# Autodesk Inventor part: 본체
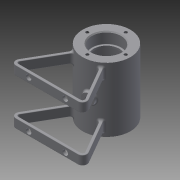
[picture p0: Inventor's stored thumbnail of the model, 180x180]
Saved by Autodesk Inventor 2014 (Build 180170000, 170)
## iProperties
Created: 2016-03
Part Number: 본체
Material: Generic
Document SubType Name: Modeling
Designer: user
Density: 1 g/cm^3
Appearance: Default
Author: user
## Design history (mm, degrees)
sketch "Sketch1"
  geometry: C1 r 26 at (0, 0); 1 further point
  constraints: 1 centre point, 1 coincident
  dimensions: "d0" = 52 diameter of C1
extrude "Extrusion1" new body sketch "Sketch1" stored distance "d1" = 70; taper "d2" = 0 deg
sketch "Sketch2"
  geometry: L1 (-26, -35)-(26, -35) reference; L2 (26, 35)-(-26, 35) reference; L3 (0, -35)-(18.15, -35); L4 (0, -21)-(21, -21); L5 (21, -21)-(21, 21); L6 (21, 21)-(0, 21); L7 (0, 21)-(0, -21); L8 (26, -35)-(-26, -35) reference; L9 (-26, -35)-(-26, 35) reference; L10 (-26, 35)-(26, 35) reference; L11 (26, 35)-(26, -35) reference; 2 further points
  constraints: 10 end point, 2 midpoint, 2 parallel, 1 coincident, 1 horizontal, 1 perpendicular, 1 point on line
  dimensions: "d3" = 21 distance between parallel lines of L7 L5; "d4" = 42 distance of L4.end L5.end
  node "Project Cut Edges1"
revolve "Revolution1" stored, may be unused: angle "d5" = 90 deg
sketch "Sketch3"
  geometry: C1 r 26 at (0, 0) reference
hole "Hole1" sketch "Sketch3" at (0, 0) diameter "d6" = 28; stored, may be unused: countersink angle "d10" = 90 deg, drill point angle "d12" = 0 deg; dims "d7" = 6, "d8" = 32, "d9" = 12, "d11" = 14
mirror "Mirror1"
sketch "Sketch4" dims "d13" = 42
  geometry: L1 (0, 0)-(0, 21); C1 r 26 at (0, 0) reference; 1 further point
  constraints: 2 end point, 1 coincident, 1 vertical, 1 vertical alignment, 3 other
hole "Hole2" sketch "Sketch4" at (0, 21) diameter "d14" = 3.242; stored, may be unused: countersink angle "d18" = 90 deg, drill point angle "d20" = 118 deg; dims "d15" = 8, "d16" = 32, "d17" = 12, "d19" = 10
pattern_circular "Circular Pattern1" dims angle "d22" = 360 deg
mirror "Mirror2"
chamfer "Chamfer1" distance "d24" = 1; stored, may be unused: second distance "d25" = 2, angle "d26" = 45 deg
fillet "Fillet1" dims "d27" = 0.3
fillet "Fillet2" dims "d28" = 3
workplane "Work Plane1"
sketch "Sketch5"
  geometry: C1 r 5 at (0, 0); 1 further point
  constraints: 1 centre point, 1 coincident
  dimensions: "d30" = 10 diameter of C1
extrude "Extrusion2" join sketch "Sketch5" stored distance "d31" = 70; taper "d32" = 0 deg
sketch "Sketch6"
  geometry: C1 r 5 at (0, 0) reference
hole "Hole3" sketch "Sketch6" at (0, 0) diameter "d33" = 5.188; stored, may be unused: countersink angle "d37" = 90 deg, drill point angle "d39" = 0 deg; dims "d34" = 8, "d35" = 32, "d36" = 12, "d38" = 10
fillet "Fillet3" dims "d40" = 2
sketch "Sketch7"
  geometry: L1 (0, 0)-(7.506, -28.012); L2 (-2.594, 29)-(-2.594, 20.839) reference; L3 (2.594, 20.839)-(2.594, 29) reference; L4 (2.594, 29)-(5, 29) reference; L5 (5, 29)-(5, 27.111) reference; L6 (-5, 27.111)-(-5, 29) reference; L7 (-5, 29)-(-2.594, 29) reference; L8 (0, 31.416)-(0, -33.389); L9 (7.506, -28.012)-(1.71, -29.565); L10 (1.71, -29.565)-(-0.587, -20.992); A1 r 21 centre (0, 0) between (-2.594, 20.839) and (2.594, 20.839) reference; A2 r 26 centre (0, 0) between (-6.5, 25.174) and (6.5, 25.174) reference; A3 r 21 centre (0, 0) between (-0.587, -20.992) and (5.435, -20.284)
  constraints: 10 end point, 3 point on circle, 2 perpendicular, 1 centre point, 1 coincident, 1 parallel, 1 point on line, 2 other
  dimensions: "d41" = 15 deg angle of L8 L1; "d42" = 29 distance of L1.end L1.start; "d75" = 12 diameter of L10 L1
revolve "Revolution2" sketch "Sketch7" stored, may be unused: angle "d43" = 90 deg
sketch "Sketch8"
  geometry: C1 r 6 at (0, 0) reference
revolve "Revolution3" stored, may be unused: angle "d44" = 90 deg
hole "Hole4" sketch "Sketch8" diameter "d45" = 5.188; stored, may be unused: countersink angle "d49" = 90 deg, drill point angle "d51" = 0 deg; dims "d46" = 8, "d47" = 32, "d48" = 12, "d50" = 10
fillet "Fillet4" dims "d52" = 2
workplane "Work Plane2"
sketch "Sketch9"
  geometry: L1 (-16.613, -20)-(-38.264, -57.5); L2 (-33.934, -65)-(0, -65); L3 (0, -67.231)-(0, 0); L4 (-14.183, -21.791)-(-35.666, -59); L5 (-33.934, -62)-(0, -62); L6 (16.613, -20)-(38.264, -57.5); L7 (33.934, -65)-(0, -65); L8 (14.183, -21.791)-(35.666, -59); L9 (33.934, -62)-(0, -62); A1 r 26 centre (0, 0) between (-16.613, -20) and (-14.183, -21.791) reference; A2 r 5 centre (-33.934, -60) between (-38.264, -57.5) and (-33.934, -65); A3 r 2 centre (-33.934, -60) between (-35.666, -59) and (-33.934, -62); A4 r 5 centre (33.934, -60) between (33.934, -65) and (38.264, -57.5); A5 r 2 centre (33.934, -60) between (33.934, -62) and (35.666, -59); A6 r 26 centre (0, 0) between (14.183, -21.791) and (16.613, -20); A7 r 26 centre (0, 0) between (-16.613, -20) and (-14.183, -21.791); 1 further point
  constraints: 18 end point, 14 point on circle, 7 symmetric about line, 6 centre point, 2 point on line, 2 tangent, 1 coincident, 1 horizontal, 1 vertical, 2 other
  dimensions: "d54" = 5 radius of A2; "d56" = 30 deg angle of L3 L1; "d57" = 45 distance from line of L2 L1.start; "d58" = 65 distance from line of L2 L3.end; "d59" = 3 distance between parallel lines of L4 L1
extrude "Extrusion3" join sketch "Sketch9" distance "d60" = 10; taper "d61" = 0 deg
mirror "Mirror3"
fillet "Fillet5" dims "d62" = 0.5
sketch "Sketch10"
  geometry: L1 (67.868, -9)-(0, -9) reference; L2 (67.868, -9)-(67.868, 0) reference; L3 (33.934, -29.5)-(33.934, 9.058); L4 (33.934, -4)-(13.934, -4); 2 further points
  constraints: 4 end point, 1 coincident, 1 parallel, 1 perpendicular, 1 point on line, 1 symmetric about line
  dimensions: "d63" = 20 distance of L4.start L4.end; "d64" = 5 distance between parallel lines of L4 L1
hole "Hole5" sketch "Sketch10" at (13.934, -4), (53.934, -4) diameter "d65" = 6; stored, may be unused: countersink angle "d69" = 90 deg, drill point angle "d71" = 0 deg; dims "d66" = 8, "d67" = 32, "d68" = 12, "d70" = 3
mirror "Mirror4"
workplane "Work Plane3"
fillet "Fillet6" dims "d73" = 3
body "Solid1"
node "Project Cut Edges2"
other parameters: "d29" = 29, "d72" = -26
